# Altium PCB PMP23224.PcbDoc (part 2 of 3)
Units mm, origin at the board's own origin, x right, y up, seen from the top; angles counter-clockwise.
Board outline 180 x 75 mm, 4 copper layers (Top Layer, Signal Layer 1, Signal Layer 2, Bottom Layer), stack 1.565 mm thick; 189 components, 98 nets, 443 pads, 89 vias.
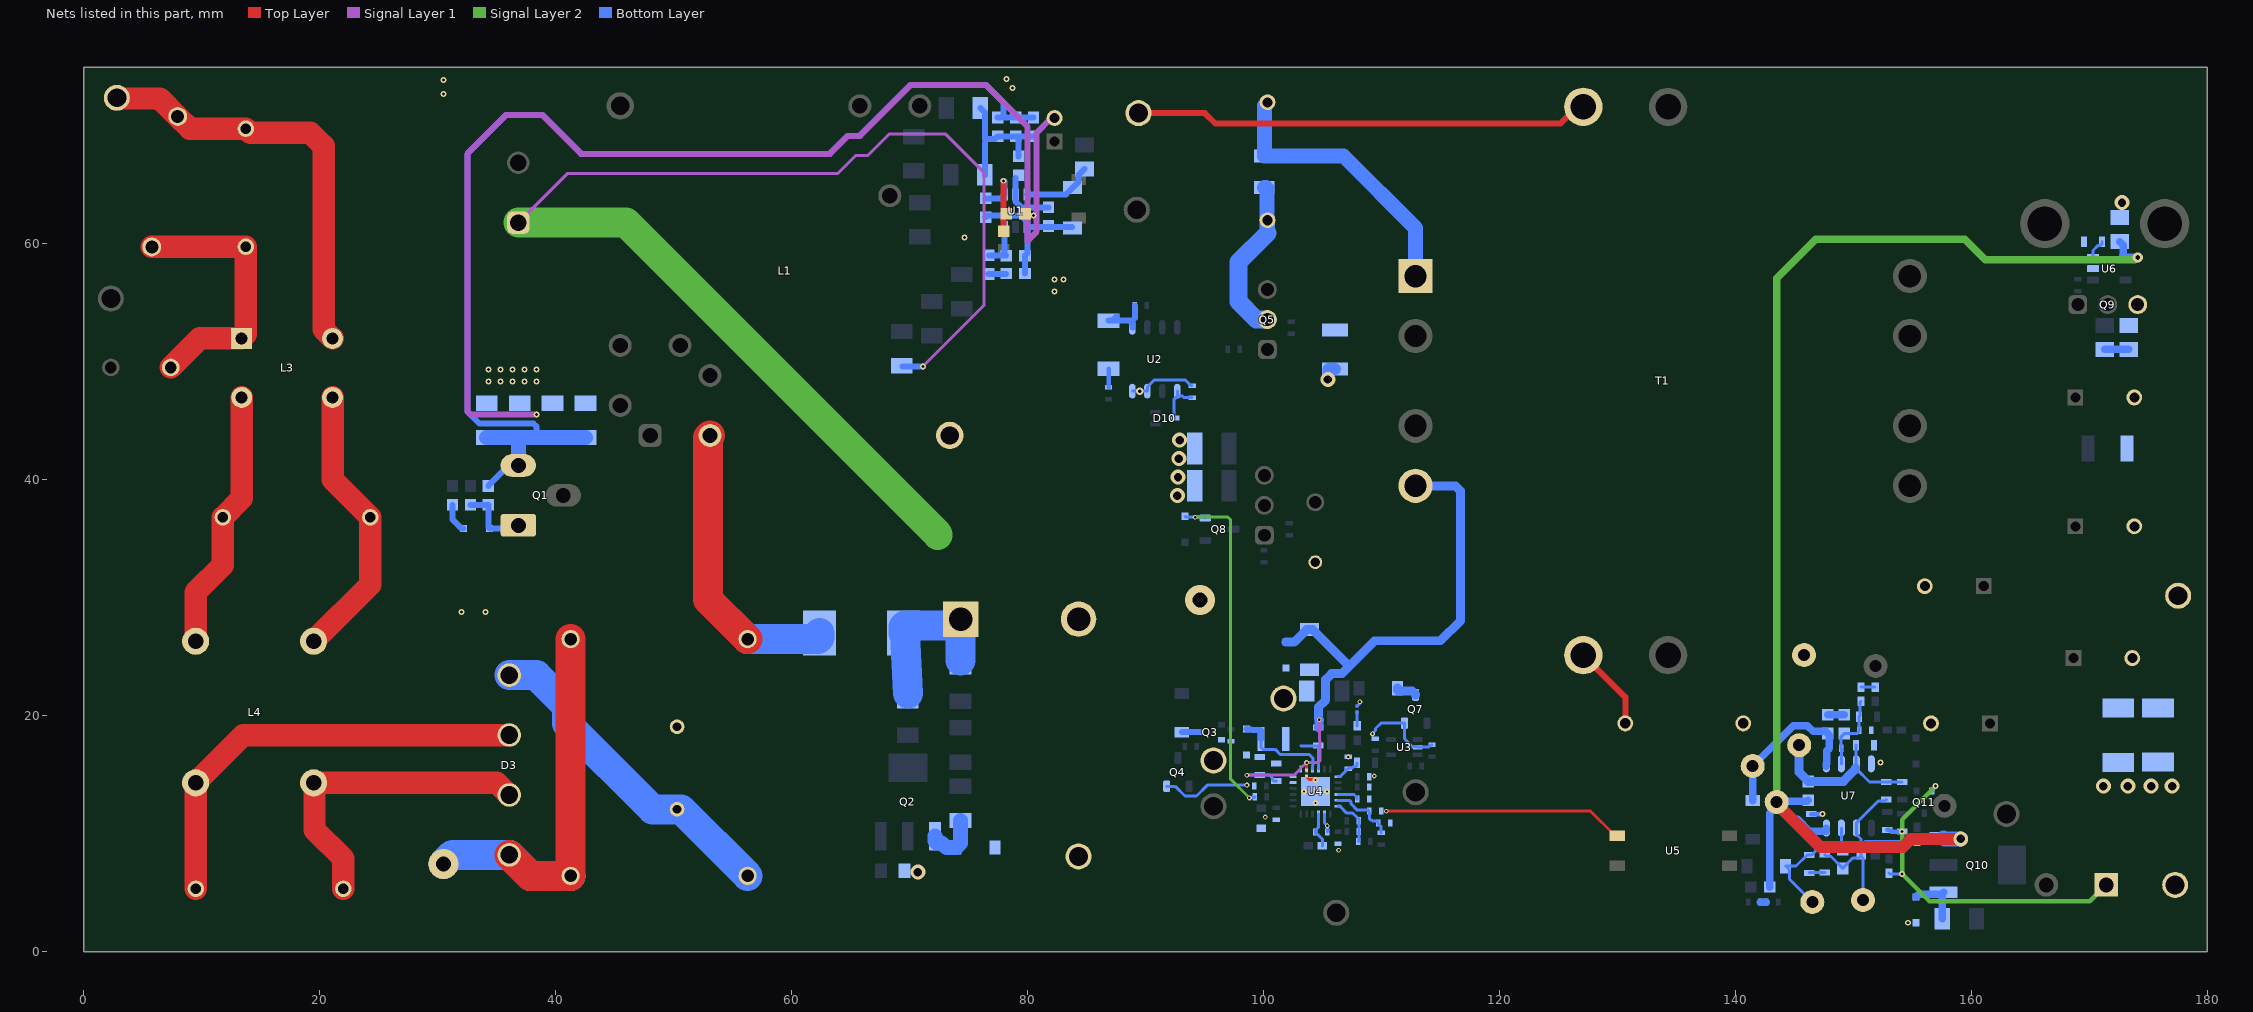
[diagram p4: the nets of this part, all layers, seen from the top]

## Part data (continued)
C2: library part 890324023025CS, "CAP, Film, 0.22 µF, X2 275 VAC, +/- 10%, TH", Cap_Case=13x7x12, Manufacturer="Wurth Elektronik", Tolerance_%=10, ValueDisplayed=0.22µF
C3 C4: "CAP, Film, 0.47 µF, X2 275 VAC, +/- 10%, TH", Cap_Case=15x10x16mm, Manufacturer="Wurth Elektronik", Supplier Part Number 1=732-5890-ND, Tolerance_%=10, ValueDisplayed=0.47µF
C5 C6: library part CMP-0012307-3, "CAP, Film, 1 uF, 450 V, +/- 5%, TH", Cap_Case=18x9.5mm, Manufacturer=Rubycon, Supplier Part Number 1=1189-1822-ND, Tolerance_%=5%, Value1=Unknown, Value2=450V, ValueDisplayed=1uF
C7: "CAP, CERM, 10 pF, 1000 V,+/- 5%, C0G/NP0, 1206", Cap_Case=1206, Manufacturer=Vishay-Vitramon, Supplier Part Number 1=720-1010-1-ND, TempCo=C0G/NP0, Tolerance_%=5, Value2=1000V, ValueDisplayed=10pF
C8: "CAP, CERM, 3900 pF, 25 V,+/- 10%, X7R, 0603", Cap_Case=0603, Manufacturer=MuRata, Supplier Part Number 1=GRM188R71E392KA01D-ND, TempCo=X7R, Tolerance_%=10, Value2=25V, ValueDisplayed=3900pF
C9: "CAP, CERM, 560 pF, 50 V,+/- 5%, C0G/NP0, 0603", Cap_Case=0603, Manufacturer=AVX, Supplier Part Number 1=478-1184-1-ND, TempCo=C0G/NP0, Tolerance_%=5, Value1="0.059 ohm", Value2=50V, ValueDisplayed=560pF
C10: "CAP, CERM, 0.22 µF, 16 V,+/- 10%, X7R, 0603", Cap_Case=0603, Manufacturer="Wurth Elektronik", Supplier Part Number 1=710-885012206048, TempCo=X7R, Tolerance_%=10, Value2=16V, ValueDisplayed=0.22µF
C11: "CAP, AL, 10 µF, 50 V, +/- 20%, TH", Cap_Case=5x11mm, Manufacturer=Panasonic, Supplier Part Number 1=P5567-ND, Tolerance_%=20, Value2=50V, ValueDisplayed=10µF
C12: "CAP, CERM, 0.068 µF, 50 V,+/- 10%, X5R, 0603", Cap_Case=0603, Manufacturer=TDK, Supplier Part Number 1=445-14157-1-ND, TempCo=X5R, Tolerance_%=10, Value1="0.035979 ohm", Value2=50V, ValueDisplayed=0.068µF
C13: "CAP, CERM, 0.47 µF, 50 V,+/- 10%, X7R, AEC-Q200 Grade 1, 1206", Cap_Case=1206, Manufacturer=TDK, Supplier Part Number 1=445-5700-1-ND, TempCo=X7R, Tolerance_%=10, Value1="0.009426 ohm", Value2=50V, ValueDisplayed=0.47µF
C14: "CAP, CERM, 10 pF, 10 V,+/- 10%, X7R, 0603", Cap_Case=0603, Manufacturer=AVX, Supplier Part Number 1=0603ZC100KAT2A-ND, TempCo=X7R, Tolerance_%=10, Value1=Unknown, Value2=10V, ValueDisplayed=10pF
C15: "CAP, CERM, 1000 pF, 100 V,+/- 10%, X7R, 0603", Cap_Case=0603, Manufacturer=AVX, Supplier Part Number 1=478-1199-1-ND, TempCo=X7R, Tolerance_%=10, Value1="0.276 ohm", Value2=100V, ValueDisplayed=1000pF
C16: library part CMP-0007728-2, "CAP, CERM, 1 uF, 25 V, +/- 10%, X7R, 0805", Cap_Case=0805, Manufacturer=Kemet, Supplier Part Number 1=399-8004-1-ND, TempCo=X7R, Tolerance_%=10%, Value1=Unknown, Value2=25V, ValueDisplayed=1uF
C17: library part CMP-0009076-1, "CAP, CERM, 0.1 uF, 630 V, +/- 10%, X7R, 1210", Cap_Case=1210, Manufacturer=Kemet, Supplier Part Number 1=399-13490-1-ND, TempCo=X7R, Tolerance_%=10%, Value1=Unknown, Value2=630V, ValueDisplayed=0.1uF
C18: library part CMP-0012326-3, "CAP, Film, 0.47 uF, 250 V, +/- 10%, TH", Cap_Case="Radial 13x6x12mm", Manufacturer=TDK, Supplier Part Number 1=495-2440-ND, Tolerance_%=10%, Value1=Unknown, Value2=250V, ValueDisplayed=0.47uF
C19: library part CMP-0006669-2, "CAP, CERM, 0.047 uF, 25 V, +/- 10%, X7R, 0402", Cap_Case=0402, Manufacturer=MuRata, Supplier Part Number 1=490-3254-1-ND, TempCo=X7R, Tolerance_%=10%, Value1=Unknown, Value2=25V, ValueDisplayed=0.047uF
C20: library part CMP-0006658-2, "CAP, CERM, 0.01 uF, 25 V, +/- 10%, X7R, 0402", Cap_Case=0402, Manufacturer=MuRata, Supplier Part Number 1=490-1312-1-ND, TempCo=X7R, Tolerance_%=10%, Value1=Unknown, Value2=25V, ValueDisplayed=0.01uF
C21: library part CMP-0086279-1, "CAP, CERM, 2200 pF, 250 V,+/- 20%, E, Dia 9mm", Cap_Case=9x4mm, Manufacturer=MuRata, TempCo=E, Tolerance_%=20%, Value2=250V, ValueDisplayed=2200pF
C22: library part CMP-0008655-2, "CAP, CERM, 33 µF, 25 V, +/- 20%, X5R, 1206", Cap_Case=1206_180, Manufacturer=TDK, Supplier Part Number 1=445-8046-1-ND, TempCo=X5R, Tolerance_%=20%, Value1="0.002648 ohm", Value2=25V, ValueDisplayed=33uF
C23 C25: library part CMP-0007355-3, "CAP, CERM, 10 uF, 35 V, +/- 20%, X5R, 0603", Cap_Case=0603, Manufacturer=Nichicon, TempCo=X5R, Tolerance_%=20%, Value1=Unknown, Value2=35V, ValueDisplayed=10uF
C24: library part CMP-0007009-5, "CAP, CERM, 6.8 µF, 25 V, +/- 10%, X5R, 0603", Cap_Case=0603, Manufacturer=TDK, Supplier Part Number 1=445-14145-6-ND, TempCo=X5R, Tolerance_%=10%, Value1="0.004211 ohm", Value2=25V, ValueDisplayed=6.8uF
C26: library part CMP-0006441-2, "CAP, CERM, 24 pF, 50 V, +/- 5%, C0G/NP0, 0402", Cap_Case=0402, Manufacturer=MuRata, Supplier Part Number 1=81-GRM1555C1H240JA1D, TempCo=C0G/NP0, Tolerance_%=5%, Value1=Unknown, Value2=50V, ValueDisplayed=24pF
C27: library part CMP-0006687-2, "CAP, CERM, 330 pF, 50 V, +/- 10%, X7R, 0402", Cap_Case=0402, Manufacturer=MuRata, Supplier Part Number 1=490-3247-1-ND, TempCo=X7R, Tolerance_%=10%, Value1=Unknown, Value2=50V, ValueDisplayed=330pF
C28: library part CMP-0006608-2, "CAP, CERM, 1 µF, 25 V, +/- 10%, X5R, 0402", Cap_Case=0402, Manufacturer=MuRata, Supplier Part Number 1=490-10017-1-ND, TempCo=X5R, Tolerance_%=10%, Value1=Unknown, Value2=25V, ValueDisplayed=1uF
C29 C30 C31: library part CMP-0006410-2, "CAP, CERM, 100 pF, 50 V, +/- 5%, C0G/NP0, 0402", Cap_Case=0402, Manufacturer=MuRata, Supplier Part Number 1=81-GRM1555C1H101JA1D, TempCo=C0G/NP0, Tolerance_%=5%, Value1=Unknown, Value2=50V, ValueDisplayed=100pF
C32: library part CMP-0006648-2, "CAP, CERM, 0.22 µF, 16 V, +/- 10%, X7R, 0402", Cap_Case=0402, Manufacturer=MuRata, Supplier Part Number 1=490-5418-1-ND, TempCo=X7R, Tolerance_%=10%, Value1=Unknown, Value2=16V, ValueDisplayed=0.22uF
C33: library part CMP-0009103-1, "CAP, CERM, 10 uF, 50 V, +/- 10%, X5R, 1210", Cap_Case=1210, Manufacturer=TDK, Supplier Part Number 1=445-9074-6-ND, TempCo=X5R, Tolerance_%=10%, Value1=Unknown, Value2=50V, ValueDisplayed=10uF
C34 C35 C36 C37 C38: library part CMP-0010480-1, "CAP, AL, 470 uF, 25 V, +/- 20%, AEC-Q200 Grade 2, TH", Cap_Case=10x16mm, Manufacturer=Chemi-Con, Supplier Part Number 1=565-1958-ND, Tolerance_%=20%, Value1=Unknown, Value2=25V, ValueDisplayed=470uF
C39: library part CMP-0081666-1, "CAP, CERM, 330 pF, 250 V,+/- 5%, C0G/NP0, 0805", Cap_Case=0805, Manufacturer=MuRata, Supplier Part Number 1=490-14654-1-ND, TempCo=C0G/NP0, Tolerance_%=5%, Value2=250V, ValueDisplayed=330pF
C40: library part CMP-0075366-1, "CAP, CERM, 2.2 µF, 25 V,+/- 10%, X7S, 0603", Cap_Case=0603, Manufacturer=MuRata, Supplier Part Number 1=490-12732-1-ND, TempCo=X7S, Tolerance_%=10%, Value2=25V, ValueDisplayed=2.2µF
C41 C47 C48: library part CMP-0007405-4, "CAP, CERM, 1 uF, 25 V, +/- 10%, X7R, 0603", Cap_Case=0603, Manufacturer=MuRata, PartNumber=GRM188R71E105KA12D, Supplier Part Number 1=490-5307-1-ND, TempCo=X7R, Tolerance_%=10%, Value1=Unknown, Value2=25V, ValueDisplayed=1uF
C42: library part CMP-0007832-2, "CAP, CERM, 1 uF, 50 V, +/- 10%, X5R, 0805", Cap_Case=0805, Manufacturer=TDK, Supplier Part Number 1=445-7622-1-ND, TempCo=X5R, Tolerance_%=10%, Value1="0.008782 ohm", Value2=50V, ValueDisplayed=1uF
C43: library part CMP-0006377-1, "CAP, CERM, 33 pF, 25 V, +/- 5%, C0G/NP0, 0402", Cap_Case=0402, Manufacturer=MuRata, Supplier Part Number 1=81-GRM1555C1E330JA1D, TempCo=C0G/NP0, Tolerance_%=5%, Value1=Unknown, Value2=25V, ValueDisplayed=33pF
C44: library part CMP-0006686-1, "CAP, CERM, 2700 pF, 50 V, +/- 10%, X7R, 0402", Cap_Case=0402, Manufacturer=MuRata, Supplier Part Number 1=490-1306-1-ND, TempCo=X7R, Tolerance_%=10%, Value1=Unknown, Value2=50V, ValueDisplayed=2700pF
C45: library part CMP-0006681-2, "CAP, CERM, 0.018 uF, 50 V, +/- 10%, X7R, 0402", Cap_Case=0402, Manufacturer=MuRata, Supplier Part Number 1=GRM155R71H183KA12D-ND, TempCo=X7R, Tolerance_%=10%, Value1=Unknown, Value2=50V, ValueDisplayed=0.018uF
C46: library part CMP-0007377-1, "CAP, CERM, 0.01 uF, 16 V, +/- 10%, X7R, 0603", Cap_Case=0603, Manufacturer=MuRata, Supplier Part Number 1=490-1525-1-ND, TempCo=X7R, Tolerance_%=10%, Value1=Unknown, Value2=16V, ValueDisplayed=0.01uF
C49: library part CMP-0007403-2, "CAP, CERM, 0.01 uF, 25 V, +/- 10%, X7R, 0603", Cap_Case=0603, Manufacturer=MuRata, Supplier Part Number 1=490-1520-1-ND, TempCo=X7R, Tolerance_%=10%, Value1=Unknown, Value2=25V, ValueDisplayed=0.01uF
D1: library part CMP-0076883-2, "Diode, Switching, 800 V, 3 A, SMC", Manufacturer=Vishay-Semiconductor, Value1=3A, Value2=1.3V
D2: library part STTH506DTI, "DIODE GEN PURP 600V 8A TO220FP", Manufacturer=STMicroelectronics
D3: library part CMP-0029222-2, "Diode, Switching-Bridge, 420 V, 8 A, TH", Manufacturer="Micro Commercial Components", Supplier Part Number 1=GBU8J-BPMS-ND, Value1=8A, Value2=1V
D4: "Diode, Switching, 100 V, 0.2 A, SOD-323", Manufacturer="Micro Commercial Components", Supplier Part Number 1=MMDL914-TPMSCT-ND, Value1=0.2A, Value2=1V
D5: "Diode, Switching, 100 V, 0.15 A, SOD-123FL", Manufacturer=Vishay-Semiconductor, Supplier Part Number 1=1N4148WFL-G3-08GICT-ND, Value1=0.15A, Value2=1.2V
D6: library part CMP-0085137-1, "Diode, Zener, 16 V, 500 mW, SOD-123", Manufacturer="Diodes Inc.", Power_W=500mW, Value1=0.5W
D7: library part CMP-0076920-2, "Diode, Switching, 100 V, 0.15 A, SOD-123FL", Manufacturer=Vishay-Semiconductor, Value1=0.15A, Value2=1.2V
D8: library part CMP-0029162-1, "Diode, Ultrafast, 600 V, 1 A, AEC-Q101, SMAF", Manufacturer="Fairchild Semiconductor", Supplier Part Number 1=ES1JAFCT-ND, Value1=1A, Value2=1.7V
D9: library part CMP-0077074-2, "Diode, Superfast Rectifier, 600 V, 1 A, 3.5x1.6mm", Manufacturer="Comchip Technology", Value1=1A, Value2=1.7V
D10: library part CMP-0028454-2, "Diode, Schottky, 30 V, 0.2 A, SOT-523", Manufacturer="Diodes Inc.", Value1=0.2A, Value2=0.7V
D11: library part CMP-0029031-1, "Diode, Switching, 200 V, 0.2 A, SOD-123", Manufacturer="Diodes Inc.", Supplier Part Number 1=BAV21W-FDICT-ND, Value1=0.2A, Value2=1.25V
D12: library part CMP-0028882-2, "Diode, Schottky, 30 V, 0.8 A, SOD-323", Manufacturer=Toshiba, Supplier Part Number 1=CUS08F30H3FDKR-ND, Value1=0.8A
D13: library part CMP-0005823-4, "Diode, TVS, Uni, 24 V, 49 Vc, SOD-323", Manufacturer=Bourns, Value1=500W
D14: library part CMP-0005822-3, "Diode, TVS, Bi, 18 V, SOD-323", Manufacturer=Bourns, Value1=350W
D15: library part CMP-0005911-2, "Diode, Zener, 20 V, 150 mW, SOD-523F", Manufacturer="Comchip Technology", Power_W=150mW, Supplier Part Number 1=641-1043-1-ND, Value1=0.15W
D16: library part CMP-0005855-3, "Diode, Zener, 5.6 V, 200 mW, SOD-323", Manufacturer="Diodes Inc.", Power_W=200mW, Value1=0.2W
D17 D18: library part CMP-0076981-2, "Diode, Switching, 100 V, 0.2 A, SOD-123", Manufacturer="ON Semiconductor", Value1=0.2A, Value2=V
D19: library part CMP-0005829-1, "Diode, Zener, 10 V, 200 mW, SOD-323", Manufacturer="Diodes Inc.", Power_W=200mW, Supplier Part Number 1=MMSZ5240BS-FDICT-ND, Value1=0.2W
F1: "Fuse, 5 A, 250VAC/VDC, TH", Irating_A=5A, Manufacturer=Littelfuse, Supplier Part Number 1=WK4263CT-ND
H1: library part CMP-0004015-1, "Heat Sink, TO-220, TH", Manufacturer="Wakefield Solutions", PartNumber=634-10ABP, Supplier Part Number 1=345-1026-ND
J1: library part CMP-0074910-1, "Terminal Block, 5.08 mm, 2x1, Brass, TH", Color=Blue, Current_A=15A, Manufacturer="On-Shore Technology", Supplier Part Number 1=ED1609-ND, Voltage_V=300V
L1: library part CMP-0078769-1, "Inductor, 120 µH, 4 A, 0.055 ohm, TH", Manufacturer="Wurth Elektronik", Value1="0.055 ohm", Value2=4A, ValueDisplayed=120µH
L2: library part 7447020, "100µH Unshielded Toroidal Inductor 2A 80 mOhm Max Radial", Manufacturer="Wurth Elektronik", Supplier Part Number 1=732-1424-ND, Value1="0.16 ohm", Value2=2A, ValueDisplayed=100µH
L3: "Coupled inductor, 1 mH, 3 A, 0.035 ohm, TH", Manufacturer="Wurth Elektronik", Supplier Part Number 1=732-1439-ND, ValueDisplayed=1mH
L4: "Coupled inductor, 10 mH, 3 A, 0.105 ohm, TH", Manufacturer="Wurth Elektronik", Supplier Part Number 1=732-1452-ND, ValueDisplayed=10mH
L5: library part CMP-0060002-1, "Inductor, Wirewound, 22 uH, 0.49 A, 0.56 ohm, SMD", Manufacturer="Taiyo Yuden", Supplier Part Number 1=587-2439-1-ND, Value1="0.56 ohm", Value2=0.49A, ValueDisplayed=22uH
NT1 NT2: library part CMP-0078142-1, "Single point connection between nets.", Manufacturer=N/A
Q1: library part IPP60R099C7XKSA1, "MOSFET, N-CH, 600 V, 22 A, TO-220AB", Alternate Manufacturer=None, Manufacturer="Infineon Technologies", Supplier Part Number 1=IPP60R099C7XKSA1-ND, Value1="? ohm", Value2="42 nC"
Q2: library part CMP-0001204-2, "MOSFET, N-CH, 600 V, 0.3 A, SOT-223", Alternate Manufacturer=None, Manufacturer=STMicroelectronics, Supplier Part Number 1=497-3523-1-ND, Value2="4.9 nC"
Q3: library part CMP-0000015-1, "MOSFET, P-CH, -50 V, -0.13 A, SOT-323", Alternate Manufacturer=None, Manufacturer="Diodes Inc.", Supplier Part Number 1=BSS84W-FDICT-ND, Value1=1
Q4: library part CMP-0085603-1, "MOSFET, N-CH, 60 V, 0.115 A, AEC-Q101, SOT-23", Alternate Manufacturer=None, Manufacturer="Diodes Inc.", Value1="? ohm", Value2="0.223 nC"
Q5 Q6: library part CMP-0084435-1, "MOSFET, N-CH, 650 V, 9 A", Alternate Manufacturer=None, Manufacturer="Infineon Technologies", Value1="? ohm", Value2="18 nC"
Q7: library part CMP-0000947-1, "MOSFET, N-CH, 100 V, 0.17 A, SOT-23", Alternate Manufacturer=None, Manufacturer="Fairchild Semiconductor", Supplier Part Number 1=BSS123NCT-ND, Value1=1, Value2="1.8 nC"
Q8: library part CMP-0067574-2, "MOSFET, N-CH, Depletion Mode, 100 V, 0.17 A, AEC-Q101, SOT-23", Alternate Manufacturer=None, Manufacturer="Infineon Technologies", Supplier Part Number 1=BSS126H6327XTSA2CT-ND, Value1="? ohm", Value2="1.4 nC"
Q9: library part CMP-0860023-1, "MOSFET, N-CH, 200 V, 100 A,", Alternate Manufacturer=None, Manufacturer="Infineon Technologies", Value1="? ohm", Value2="70 nC"
Q10: library part CMP-0000473-1, "Transistor, NPN, 100 V, 1 A, AEC-Q101, SOT-223", Manufacturer="Diodes Inc.", Supplier Part Number 1=FZT493CT-ND, Value1="1 A", Value2=300
Q11: library part CMP-0000774-1, "MOSFET, N-CH, 60 V, 0.31 A, SOT-323", Alternate Manufacturer=None, Manufacturer="Fairchild Semiconductor", Supplier Part Number 1=2N7002KWCT-ND, Value1=1
R1 R6: "RES, 3.09 M, 1%, 0.25 W, 1206", Manufacturer=Vishay-Dale, Power_W=0.25, Supplier Part Number 1=541-3.09MFCT-ND, TempCo="100 ppm/C", Tolerance_%=1, Value1=1%, Value2=0.25W, Value_Code=3M09, ValueDisplayed=3.09M
R2 R5 R9 R15: "RES, 3.3 M, 5%, 0.25 W, 1206", Manufacturer=Vishay-Dale, Power_W=0.25, Supplier Part Number 1=541-3.3MECT-ND, TempCo="200 ppm/C", Tolerance_%=5, Value1=5%, Value2=0.25W, Value_Code=3M30, ValueDisplayed=3.3M
R3: "RES, 10.0, 1%, 0.1 W, 0603", Manufacturer=Vishay-Dale, Power_W=0.1, Supplier Part Number 1=541-10.0HCT-ND, TempCo="100 ppm/C", Tolerance_%=1, Value1=1%, Value2=0.1W, Value_Code=10R0, ValueDisplayed=10.0
R4: "RES, 82.5 k, 1%, 0.1 W, 0603", Manufacturer=Vishay-Dale, Power_W=0.1, Supplier Part Number 1=541-82.5KHCT-ND, TempCo="100 ppm/C", Tolerance_%=1, Value1=1%, Value2=0.1W, Value_Code=82k5, ValueDisplayed=82.5k
R7: "RES, 1.00, 1%, 0.1 W, 0603", Manufacturer=Vishay-Dale, Power_W=0.1, Supplier Part Number 1=52K8059, TempCo="100 ppm/C", Tolerance_%=1, Value1=1%, Value2=0.1W, Value_Code=1R00, ValueDisplayed=1.00
R8: "RES, 24.3 k, 1%, 0.1 W, 0603", Manufacturer=Vishay-Dale, Power_W=0.1, Supplier Part Number 1=541-24.3KHCT-ND, TempCo="100 ppm/C", Tolerance_%=1, Value1=1%, Value2=0.1W, Value_Code=24k3, ValueDisplayed=24.3k
R10: "RES, 3.0 k, 5%, 0.1 W, 0603", Manufacturer=Vishay-Dale, Power_W=0.1, Supplier Part Number 1=541-3.0KGCT-ND, TempCo="200 ppm/C", Tolerance_%=5, Value1=5%, Value2=0.1W, Value_Code=3k00, ValueDisplayed=3.0k
R11 R12: "RES, 0.13, 1%, 0.5 W, 1206", Manufacturer="Stackpole Electronics Inc", Power_W=0.5, Supplier Part Number 1=CSR1206FTR130CT-ND, TempCo="100 ppm/C", Tolerance_%=1, Value1=1%, Value2=0.5W, Value_Code=R130, ValueDisplayed=0.13
R13 R14: "RES, 0.15, 1%, 0.5 W, 1206", Manufacturer=Panasonic, Power_W=0.5, Supplier Part Number 1=P16006CT-ND, TempCo="250 ppm/C", Tolerance_%=1, Value1=1%, Value2=0.5W, Value_Code=R150, ValueDisplayed=0.15
R16: library part CMP-0022260-1, "RES, 28.0 k, 1%, 0.1 W, 0603", Manufacturer=Vishay-Dale, Power_W=100mW, Supplier Part Number 1=541-28.0KHCT-ND, TempCo="100 ppm/C", Tolerance_%=1%, Value2=0.1W, Value_Code=28k0, ValueDisplayed=28.0k
R17: "RES, 10.0, 1%, 0.125 W, 0805", Manufacturer=Vishay-Dale, Power_W=0.125, Supplier Part Number 1=541-10.0CCT-ND, TempCo="100 ppm/C", Tolerance_%=1, Value1=1%, Value2=0.125W, Value_Code=10R0, ValueDisplayed=10.0
R18: "RES, 140 k, 1%, 0.1 W, 0603", Manufacturer=Vishay-Dale, Power_W=0.1, Supplier Part Number 1=541-140KHCT-ND, TempCo="100 ppm/C", Tolerance_%=1, Value1=1%, Value2=0.1W, Value_Code=140k
R19 R22 R23: library part CMP-0016959-3, "RES, 3.24 M, 1%, 0.25 W, AEC-Q200 Grade 0, 1206", Manufacturer=Vishay-Dale, Power_W=250mW, Supplier Part Number 1=541-3.24MFCT-ND, TempCo="100 ppm/C", Tolerance_%=1%, Value2=0.25W, Value_Code=3M24, ValueDisplayed=3.24M
R20: library part CMP-0017052-1, "RES, 51.1 k, 1%, 0.25 W, 1206", Manufacturer=Vishay-Dale, Power_W=250mW, Supplier Part Number 1=541-51.1KFCT-ND, TempCo="100 ppm/C", Tolerance_%=1%, Value2=0.25W, Value_Code=51k1, ValueDisplayed=51.1k
R21 R57: library part CMP-0022532-2, "RES, 60.4 k, 1%, 0.1 W, 0603", Manufacturer=Vishay-Dale, Power_W=100mW, Supplier Part Number 1=541-60.4KHCT-ND, TempCo="100 ppm/C", Tolerance_%=1%, Value2=0.1W, Value_Code=60k4, ValueDisplayed=60.4k
R24: library part CMP-0018673-3, "RES, 3.3 M, 5%, 0.25 W, AEC-Q200 Grade 0, 1206", Manufacturer=Vishay-Dale, Power_W=250mW, Supplier Part Number 1=541-3.3MECT-ND, TempCo="200 ppm/C", Tolerance_%=5%, Value2=0.25W, Value_Code=3M30, ValueDisplayed=3.3M
R25 R26: library part CMP-0025950-1, "RES, 100 k, 1%, 0.063 W, 0402", Manufacturer=Vishay-Dale, Power_W=63mW, Supplier Part Number 1=541-100KLCT-ND, TempCo="100 ppm/C", Tolerance_%=1%, Value2=0.063W, Value_Code=100k
R27: library part CMP-0026942-3, "RES, 4.7, 5%, 0.063 W, AEC-Q200 Grade 0, 0402", Manufacturer=Vishay-Dale, Power_W=63mW, Supplier Part Number 1=541-4.7JCT-ND, TempCo="200 ppm/C", Tolerance_%=5%, Value2=0.063W, Value_Code=4R70, ValueDisplayed=4.7
R28 R30: library part CMP-0026843-3, "RES, 15, 5%, 0.063 W, AEC-Q200 Grade 0, 0402", Manufacturer=Vishay-Dale, Power_W=63mW, Supplier Part Number 1=541-15JCT-ND, TempCo="200 ppm/C", Tolerance_%=5%, Value2=0.063W, Value_Code=15R0, ValueDisplayed=15
R29 R31: library part CMP-0026825-5, "RES, 10 k, 5%, 0.063 W, AEC-Q200 Grade 0, 0402", Manufacturer=Vishay-Dale, Power_W=63mW, Supplier Part Number 1=541-10KJCT-ND, TempCo="200 ppm/C", Tolerance_%=5%, Value2=0.063W, Value_Code=10k0, ValueDisplayed=10k
R32 R34: library part CMP-0026302-1, "RES, 348 k, 1%, 0.063 W, 0402", Manufacturer=Vishay-Dale, Power_W=63mW, Supplier Part Number 1=541-348KLCT-ND, TempCo="100 ppm/C", Tolerance_%=1%, Value2=0.063W, Value_Code=348k
R33: library part CMP-0026071-1, "RES, 1.00 k, 1%, 0.063 W, 0402", Manufacturer=Vishay-Dale, Power_W=63mW, Supplier Part Number 1=541-1.00KLCT-ND, TempCo="100 ppm/C", Tolerance_%=1%, Value2=0.063W, Value_Code=1k00, ValueDisplayed=1.00k
R35 R36: library part CMP-0015329-1, "RES, 0.18, 5%, 0.25 W, 1210", Manufacturer=Panasonic, Power_W=250mW, Supplier Part Number 1=P.18SCT-ND, TempCo="200 ppm/C", Tolerance_%=5%, Value2=0.25W, Value_Code=R180, ValueDisplayed=0.18
R37: library part CMP-0026402-2, "RES, 499, 1%, 0.063 W, AEC-Q200 Grade 0, 0402", Manufacturer=Vishay-Dale, Power_W=63mW, Supplier Part Number 1=541-499LCT-ND, TempCo="100 ppm/C", Tolerance_%=1%, Value2=0.063W, Value_Code=499R, ValueDisplayed=499
R38: library part CMP-0021459-2, "RES, 84.5 k, 1%, 0.125 W, 0805", Manufacturer=Vishay-Dale, Power_W=125mW, Supplier Part Number 1=541-84.5KCCT-ND, TempCo="100 ppm/C", Tolerance_%=1%, Value2=0.125W, Value_Code=84k5, ValueDisplayed=84.5k
R39: library part CMP-0026395-1, "RES, 47.5 k, 1%, 0.063 W, 0402", Manufacturer=Vishay-Dale, Power_W=63mW, Supplier Part Number 1=541-47.5KLCT-ND, TempCo="100 ppm/C", Tolerance_%=1%, Value2=0.063W, Value_Code=47k5, ValueDisplayed=47.5k
R40: library part CMP-0026859-2, "RES, 1.0 M, 5%, 0.063 W, AEC-Q200 Grade 0, 0402", Manufacturer=Vishay-Dale, Power_W=63mW, Supplier Part Number 1=541-1.0MJCT-ND, TempCo="200 ppm/C", Tolerance_%=5%, Value2=0.063W, Value_Code=1M00, ValueDisplayed=1.0M
R41: library part CMP-0026875-1, "RES, 20 k, 5%, 0.063 W, 0402", Manufacturer=Vishay-Dale, Power_W=63mW, Supplier Part Number 1=541-20KJCT-ND, TempCo="200 ppm/C", Tolerance_%=5%, Value2=0.063W, Value_Code=20k0, ValueDisplayed=20k
R42 R44: library part CMP-0026065-1, "RES, 196 k, 1%, 0.063 W, 0402", Manufacturer=Vishay-Dale, Power_W=63mW, Supplier Part Number 1=541-196KLCT-ND, TempCo="100 ppm/C", Tolerance_%=1%, Value2=0.063W, Value_Code=196k
R43 R45 R51: library part CMP-0026822-3, "RES, 0, 5%, 0.063 W, AEC-Q200 Grade 0, 0402", Manufacturer=Vishay-Dale, Power_W=63mW, Supplier Part Number 1=541-0.0JCT-ND, TempCo="200 ppm/C", Tolerance_%=5%, Value2=0.063W, Value_Code=0000, ValueDisplayed=0
R46: library part CMP-0026021-1, "RES, 150 k, 1%, 0.063 W, 0402", Manufacturer=Vishay-Dale, Power_W=63mW, Supplier Part Number 1=541-150KLCT-ND, TempCo="100 ppm/C", Tolerance_%=1%, Value2=0.063W, Value_Code=150k
R47: library part CMP-0026445-1, "RES, 53.6 k, 1%, 0.063 W, 0402", Manufacturer=Vishay-Dale, Power_W=63mW, Supplier Part Number 1=541-53.6KLCT-ND, TempCo="100 ppm/C", Tolerance_%=1%, Value2=0.063W, Value_Code=53k6, ValueDisplayed=53.6k
R48: library part CMP-0020168-2, "RES, 53.6, 0.1%, 0.125 W, 0805", Manufacturer="Yageo America", Power_W=125mW, TempCo="25 ppm/C", Tolerance_%=0.1%, Value2=0.125W, Value_Code=53R6, ValueDisplayed=53.6
R49 R50: library part CMP-0016532-1, "RES, 0.01, 1%, 1 W, 2010", Manufacturer="Stackpole Electronics Inc", Power_W=1W, Supplier Part Number 1=CSRN2010FT10L0CT-ND, TempCo="250 ppm/C", Tolerance_%=1%, Value_Code=R010, ValueDisplayed=0.01
R52: library part CMP-0025963-1, "RES, 10.0, 1%, 0.063 W, 0402", Manufacturer=Vishay-Dale, Power_W=63mW, Supplier Part Number 1=541-10.0LCT-ND, TempCo="100 ppm/C", Tolerance_%=1%, Value2=0.063W, Value_Code=10R0, ValueDisplayed=10.0
R53: library part CMP-0026329-1, "RES, 3.01 k, 1%, 0.063 W, 0402", Manufacturer=Vishay-Dale, Power_W=63mW, Supplier Part Number 1=541-3.01KLCT-ND, TempCo="100 ppm/C", Tolerance_%=1%, Value2=0.063W, Value_Code=3k01, ValueDisplayed=3.01k
R54: library part CMP-0016577-2, "RES, 10.0 k, 1%, 0.25 W, 1206", Manufacturer=Vishay-Dale, Power_W=250mW, Supplier Part Number 1=541-10.0KFCT-ND, TempCo="100 ppm/C", Tolerance_%=1%, Value2=0.25W, Value_Code=10k0, ValueDisplayed=10.0k
R55 R67: library part CMP-0021990-4, "RES, 100 k, 1%, 0.1 W, AEC-Q200 Grade 0, 0603", Manufacturer=Vishay-Dale, PartNumber=CRCW0603100KFKEA, Power_W=100mW, Supplier Part Number 1=541-100KHCT-ND, TempCo="100 ppm/C", Tolerance_%=1%, Value2=0.1W, Value_Code=100k
R56: library part CMP-0025729-1, "RES, 1.0 k, 5%, 0.1 W, 0603", Manufacturer=Vishay-Dale, Power_W=100mW, Supplier Part Number 1=541-1.0KGCT-ND, TempCo="200 ppm/C", Tolerance_%=5%, Value2=0.1W, Value_Code=1k00, ValueDisplayed=1.0k
R58: library part CMP-0025768-2, "RES, 2.0 k, 5%, 0.1 W, 0603", Manufacturer=Vishay-Dale, Power_W=100mW, Supplier Part Number 1=541-2.0KGCT-ND, TempCo="200 ppm/C", Tolerance_%=5%, Value2=0.1W, Value_Code=2k00, ValueDisplayed=2.0k
R59: library part CMP-0026022-3, "RES, 150, 1%, 0.063 W, AEC-Q200 Grade 0, 0402", Manufacturer=Vishay-Dale, Power_W=63mW, Supplier Part Number 1=541-150LCT-ND, TempCo="100 ppm/C", Tolerance_%=1%, Value2=0.063W, Value_Code=150R, ValueDisplayed=150
R60: library part CMP-0025993-1, "RES, 12.7 k, 1%, 0.063 W, 0402", Manufacturer=Vishay-Dale, Power_W=63mW, Supplier Part Number 1=541-12.7KLCT-ND, TempCo="100 ppm/C", Tolerance_%=1%, Value2=0.063W, Value_Code=12k7, ValueDisplayed=12.7k
R61 R62: library part CMP-0025686-1, "RES, 10.0 k, 0.1%, 0.1 W, AEC-Q200 Grade 1, 0603", Manufacturer=Vishay-Dale, Power_W=100mW, Supplier Part Number 1=TNP10.0KAACT-ND, TempCo="25 ppm/C", Tolerance_%=0.1%, Value2=0.1W, Value_Code=10k0, ValueDisplayed=10.0k
R63: library part CMP-0026064-2, "RES, 191, 1%, 0.063 W, 0402", Manufacturer=Vishay-Dale, Power_W=63mW, Supplier Part Number 1=541-191LCT-ND, TempCo="100 ppm/C", Tolerance_%=1%, Value2=0.063W, Value_Code=191R, ValueDisplayed=191
R64: library part CMP-0026620-1, "RES, 9.31 k, 1%, 0.063 W, 0402", Manufacturer=Vishay-Dale, Power_W=63mW, Supplier Part Number 1=541-9.31KLCT-ND, TempCo="100 ppm/C", Tolerance_%=1%, Value2=0.063W, Value_Code=9k31, ValueDisplayed=9.31k
R65: library part CMP-0023624-3, "RES, 9.76 k, 0.1%, 0.1 W, 0603", Manufacturer="Susumu Co Ltd", Power_W=100mW, Supplier Part Number 1=RG16P9.76KBCT-ND, TempCo="25 ppm/C", Tolerance_%=0.1%, Value2=0.1W, Value_Code=9k76, ValueDisplayed=9.76k
R66: library part CMP-0026455-1, "RES, 576 k, 1%, 0.063 W, 0402", Manufacturer=Vishay-Dale, Power_W=63mW, Supplier Part Number 1=541-576KLCT-ND, TempCo="100 ppm/C", Tolerance_%=1%, Value2=0.063W, Value_Code=576k
R68: library part CMP-0021998-4, "RES, 10.0 k, 1%, 0.1 W, AEC-Q200 Grade 0, 0603", Manufacturer=Vishay-Dale, PartNumber=CRCW060310K0FKEA, Power_W=100mW, Supplier Part Number 1=541-10.0KHCT-ND, TempCo="100 ppm/C", Tolerance_%=1%, Value2=0.1W, Value_Code=10k0, ValueDisplayed=10.0k
RT1: library part CMP-0002523-3, "Thermistor NTC, 47k ohm, 5%, 0603", Manufacturer=MuRata, Power_W=100mW, Supplier Part Number 1=490-2428-1-ND, Tolerance_%=5%
RV1: "Varistor 275V RMS 10MM Radial, TH", Manufacturer="EPCOS Inc", Supplier Part Number 1=495-1433-ND
T1: library part CMP-0095835-1, "Flyback for PMP23224", Manufacturer="Renco Electronics", Operating Temperature Range=to, Voltage_Isolation_Vrms=3kV
TP1 TP4 TP5 TP6 TP8 TP9 TP10: library part CMP-0055147-1, "Test Point, Multipurpose, Red, TH", Color=Red, Manufacturer=Keystone, Supplier Part Number 1=36-5010-ND
TP2 TP7 TP11 TP12: library part CMP-0055148-1, "Test Point, Multipurpose, Black, TH", Color=Black, Manufacturer=Keystone, Supplier Part Number 1=36-5011-ND
TP3: library part CMP-0003907-1, "PIGTAIL", Manufacturer="Texas Instruments"
TP13 TP14 TP15 TP16 TP18 TP19 TP20: library part CMP-0055140-1, "Test Point, Miniature, Orange, TH", Color=Orange, Manufacturer=Keystone, Supplier Part Number 1=36-5003-ND
TP17: library part CMP-0055138-1, "Test Point, Miniature, Black, TH", Color=Black, Manufacturer=Keystone, Supplier Part Number 1=36-5001-ND
TP_L1: "Test Point, Multipurpose, Red, TH", Color=Red, Manufacturer=Keystone, Supplier Part Number 1=36-5010-ND
TP_N1: library part CMP-0055148-2, "Test Point, Multipurpose, Black, TH", Color=Black, Manufacturer="Keystone Electronics", PartNumber=5011, Supplier Part Number 1=36-5011-ND
U1: "6-Pin Single-Phase Transition-Mode PFC Controller, DBV0006A (SOT-23-6)", Alternate Manufacturer="Texas Instruments"
U2: library part CMP-0077706-1, "3-kVRMS Single-Channel Isolated Gate Drivers, D0008B (SOIC-8)", Alternate Manufacturer="Texas Instruments", Alternate PartNumber=UCC5350SBD
U3: library part CMP-0860894-1, "Low power, small size comparator with push-pull output, DCK0005A (SOT-SC70-5)", Alternate Manufacturer="Texas Instruments", Alternate PartNumber=TLV7011DCKT, Operating Temperature Range="-40 to 125 C", Rating=Catalog
U4: library part CMP-0086087-1, "UCC28782ADRTW, RTW0024B (WQFN-24)", Alternate Manufacturer="Texas Instruments"
U5: library part CMP-0006160-3, "Optocoupler, 5 kV, 63-125% CTR, SMT", Manufacturer=Vishay-Semiconductor, Supplier Part Number 1=VOL618A-2TCT-ND, Voltage_Isolation_Vrms=5kV
U6: library part CMP-0013047-3, "High-Frequency Multi-Mode Synchronous Rectifier Controller, DBV0005A (SOT-23-5)", Alternate Manufacturer="Texas Instruments", Alternate PartNumber=UCC24612-2DBVR
U7: library part CMP-0043686-1, "Dual Operational Amplifier with Internal Reference, 3 to 32 V, -40 to 105 degC, 8-pin SOIC (D8), Green (RoHS & no Sb/Br)", Manufacturer="Texas Instruments", PartNumber=TL103WAID, Rating=Catalog, Total Supply Voltage(Max)(+5V is 5, +/-5V is 10)=32, Total Supply Voltage(Min)(+5V is 5, +/-5V is 10)=3

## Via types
v1: diameter 0.508, hole 0.254, Top Layer to Bottom Layer, 41 vias
v2: diameter 0.406, hole 0.203, Top Layer to Bottom Layer, 23 vias
v3: diameter 1.27, hole 0.711, Top Layer to Bottom Layer, 12 vias
v4: diameter 0.5, hole 0.2, Top Layer to Bottom Layer, 5 vias
v5: diameter 0.864, hole 0.406, Top Layer to Bottom Layer, 4 vias
v6: diameter 2.54, hole 1.27, Top Layer to Bottom Layer, 2 vias
v7: diameter 0.635, hole 0.305, Top Layer to Bottom Layer, 2 vias

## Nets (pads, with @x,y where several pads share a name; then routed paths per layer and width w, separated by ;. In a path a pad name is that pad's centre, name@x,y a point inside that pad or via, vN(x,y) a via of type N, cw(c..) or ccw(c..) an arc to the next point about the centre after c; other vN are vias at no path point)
BAT_GND: J1.1 Q11.2 R49.2 R50.2 R63.2 R65.1 R68.1 TP12.1 | length 30.4
  Signal Layer 2 w0.381: v1(156.972,14.032) 154.145,11.205 v1(154.145,10.172) v1(154.145,6.588) 156.459,4.274 170.059,4.274 J1.1@171.45,5.665
  Bottom Layer w0.254: R63.2@153.04,6.658 153.11,6.588 v1(154.145,6.588)
  Bottom Layer w0.381: R65.1@152.878,10.326 153.068,10.326 153.223,10.172 v1(154.145,10.172) ; Q11.2@156.663,13.641 156.663,13.705 156.972,14.015 v1(156.972,14.032)
  other v3: 171.196,14.032 173.282,14.032 175.26,14.032 177.038,14.032
BGND: C22.2 C23.2 C24.2 C25.2 D13.2 NT2.2 T1.4 U4.20 | length 54.2
  Top Layer w0.254: NT2.2@103.657,15.416 v2(103.657,16.034)
  Signal Layer 1 w0.254: v2(98.593,14.963) 102.586,14.963 v2(103.657,16.034) 104.653,16.034 104.801,16.183 104.801,17.867 104.734,17.935 v2(104.734,19.661)
  Bottom Layer w0.254: v2(98.593,14.963) 99.655,14.963 C24.2@99.678,14.986 100.503,14.986 100.774,14.715 100.774,14.579 100.901,14.452 C25.2@101.092,14.452 ; v2(103.657,16.034) 103.66,16.031 103.66,15.487 U4.20@103.664,15.484
  Bottom Layer w0.762: D13.2@101.926,26.246 102.606,26.246 103.664,27.304 C22.2@103.914,27.304 104.164,27.304 107.152,24.316 107.385,24.316 ; C23.2@104.664,19.004 104.727,19.067 104.727,19.655 v2(104.734,19.661) 104.664,19.73 104.664,20.726 105.266,21.329 105.266,23.072 105.773,23.579 106.648,23.579 107.385,24.316 ; T1.4@112.89,39.497 116.276,39.497 116.723,39.051 116.723,28.077 115.008,26.362 109.431,26.362 107.385,24.316
"bias 5V": C41.2 C42.1 Q10.3 R56.2 R58.2 TP14.1 U6.4 U7.8 | length 114.6
  Top Layer w1.016: TP14.1@143.51,12.701 143.51,12.56 147.18,8.89 154.223,8.89 154.896,9.562 v3(159.114,9.562)
  Signal Layer 2 w0.635: TP14.1@143.51,12.701 143.51,57.108 146.812,60.41 159.449,60.41 161.186,58.674 173.876,58.674 174.055,58.853 v5(174.117,58.853)
  Bottom Layer w0.635: R58.2@142.918,5.48 142.918,11.731 143.51,12.323 TP14.1@143.51,12.701 ; R56.2@146.182,12.834 146.116,12.767 143.577,12.767 TP14.1@143.51,12.701 ; U7.8@147.72,10.483 147.72,10.225 147.703,10.207 146.5,10.207 C41.2@146.436,10.144 146.373,10.144 145.291,11.226 144.985,11.226 TP14.1@143.51,12.701 ; C42.1@172.593,60.198 172.896,59.895 172.896,58.879 172.918,58.858 174.113,58.858 v5(174.117,58.853)
  Bottom Layer w1.27: Q10.3@157.654,9.65 157.741,9.562 v3(159.114,9.562)
BIN: C22.1 C23.1 D9.1 D13.1 L5.2 TP5.1 U4.22 | length 3.5
  Bottom Layer w0.254: 103.164,17.442 103.183,17.461 104.645,17.461 C23.1@104.664,17.48 U4.22@104.664,15.484
BSW: D12.2 L5.1 U4.21 | length 8.4
  Bottom Layer w0.254: L5.1@99.788,18.034 99.788,17.334 99.961,17.161 100.999,17.161 101.453,16.707 103.897,16.707 104.187,16.417 104.187,15.815 104.171,15.799 104.171,15.491 U4.21@104.164,15.484
  Bottom Layer w0.508: D12.2@98.552,18.88 98.598,18.834 98.988,18.834 99.042,18.78 99.742,18.78 99.788,18.734 L5.1@99.788,18.034
BUR: C30.1 R46.1 R47.1 U4.5 | length 5.7
  Bottom Layer w0.254: U4.5@106.314,12.834 107.284,12.834 107.433,12.685 107.433,12.514 107.95,11.996 108.908,11.996 108.908,11.882 108.982,11.808 108.982,11.252 109.058,11.176 109.172,11.176 109.248,11.1 109.664,11.1 109.728,11.036 R47.1@109.728,10.922 109.728,10.808 109.791,10.744 109.833,10.744 109.982,10.595 R46.1@109.982,10.068
CS: C31.2 R33.1 U4.9 | length 3.1
  Bottom Layer w0.254: U4.9@104.664,11.684 104.664,10.544 104.394,10.274 C31.2@104.394,10.16 104.394,10.046 104.457,9.982 104.572,9.982 104.994,9.56 R33.1@104.994,8.982
FB: C27.1 R40.1 R41.1 U4.6 | length 4.1
  Bottom Layer w0.254: U4.6@106.314,12.334 106.48,12.334 107.072,11.742 107.562,11.742 107.762,11.542 107.773,11.542 108.091,11.224 C27.1@108.091,11.11 R40.1@108.091,10.186 108.091,9.381 R41.1@108.042,9.332
FLT: C29.1 RT1.2 U4.1 | length 2.3
  Bottom Layer w0.254: U4.1@106.314,14.834 106.48,14.834 107.01,15.364 107.01,15.43 107.074,15.494 C29.1@107.188,15.494 107.251,15.557 107.505,15.557 107.632,15.684 107.823,15.684 107.95,15.811 RT1.2@107.95,16.002
GND: C1.2 C5.2 C6.2 C11.2 C12.2 C13.2 C14.2 C15.2 C16.2 C17.2 C20.2 C21.2 D3.4 D6.2 L1.13 NT1.2 R11.1 R12.1 R13.1 R14.1 R18.1 R21.1 R35.1 R36.1 T1.10 T1.11 TP2.1 TP3.2 TP7.1 U1.4 U2.3 U2.4 | length 206.4
  Top Layer w0.508: TP2.1@89.408,71.089 95.035,71.089 95.931,70.193 125.174,70.193 126.609,71.628 T1.10@127.114,71.628 ; T1.11@127.114,25.146 130.676,21.584 C21.2@130.676,19.358
  Top Layer w2.54: D3.4@36.068,8.209 37.846,6.431 C5.2@41.268,6.431 C6.2@41.268,26.497
  Signal Layer 1 w0.508: v1(38.354,45.547) 32.766,45.547 32.512,45.801 32.512,67.645 35.814,70.947 38.862,70.947 42.164,67.645 63.246,67.645 64.77,69.169 65.786,69.169 70.104,73.487 76.454,73.487 80.01,69.931 80.01,60.279 80.772,61.041 80.772,69.423 82.026,70.677 C11.2@82.296,70.677
  Bottom Layer w0.254: U2.4@88.884,47.527 U2.3@90.154,47.527 90.154,47.877 90.756,48.479 93.358,48.479 93.849,47.987 C20.2@93.964,47.987 ; NT1.2@107.95,20.828 108.176,21.054 v2(108.176,21.184)
  Bottom Layer w0.508: C15.2@76.454,62.273 76.579,62.398 79.452,62.398 79.944,61.906 U1.4@79.944,61.444 ; R18.1@79.794,57.485 C12.2@79.794,59.009 ; C12.2@80.01,59.225 80.01,61.378 U1.4@79.944,61.444 ; C13.2@83.749,61.444 U1.4@79.944,61.444
  Bottom Layer w1.016: v3(105.457,48.514) 105.506,48.563 105.506,49.362 105.548,49.404 C17.2@106.053,49.404
  Bottom Layer w2.54: v6(30.48,7.447) 31.242,8.209 D3.4@36.068,8.209 37.846,6.431 C5.2@41.268,6.431
  other v1: 32.004,28.783 34.036,28.783 34.29,48.341 35.306,48.341 36.322,48.341 37.338,48.341 38.354,48.341 34.29,49.357 35.306,49.357 36.322,49.357 37.338,49.357 38.354,49.357 82.296,55.961 82.296,56.977 83.058,56.977 74.676,60.533 80.518,62.393 30.48,72.719 78.74,73.233 30.48,73.914 78.232,73.995
  other v3: 70.701,6.749 92.694,38.664 92.752,40.235 92.83,41.795 92.889,43.366
  other v6: 94.636,29.806
  other v7: 89.519,47.527
GND_SEC: C21.1 C33.2 C34.2 C35.2 C36.2 C37.2 C38.2 C39.1 C40.2 C41.1 C42.2 C47.2 D16.2 Q9.3 R49.1 R50.1 R60.1 TP11.1 TP17.1 U6.2 U7.4 | length 0.9
  Bottom Layer w0.381: C41.1@146.436,11.668 v1(147.378,11.668)
  other v1: 154.653,2.456 152.298,16.025
  other v3: 172.782,63.5
HV: C1.1 C17.1 C18.1 D1.1 D2.1 R6.2 R19.2 R20.2 R24.2 T1.1 | length 149.2
  Signal Layer 1 w0.254: D2.1@36.83,61.803 41.021,65.994 63.93,65.994 65.454,67.518 66.47,67.518 68.289,69.337 73.033,69.337 76.327,66.042 76.327,54.818 v1(71.12,49.611)
  Signal Layer 2 w2.54: D2.1@36.83,61.803 45.974,61.803 72.39,35.387 72.39,35.306
  Bottom Layer w0.508: R6.2@69.416,49.611 v1(71.12,49.611)
  Bottom Layer w1.27: C18.1@100.345,72.011 100.345,71.989 100.076,71.721 R24.2@100.076,67.471 106.773,67.471 112.89,61.354 T1.1@112.89,57.277
  Bottom Layer w2.54: R20.2@69.85,21.881 69.621,26.878 D1.1@69.494,27.005 69.494,27.513 69.621,27.64 73.774,27.64 C1.1@74.328,28.194 R19.2@74.328,24.692
IC_GND: C26.2 C28.2 C29.2 C30.2 C31.1 C32.2 D15.2 NT1.1 NT2.1 Q4.2 Q7.2 R34.2 R39.1 R42.1 R43.1 R44.1 R45.2 R47.2 U3.2 U4.8 U4.17 U4.18 U4.25 U5.3 | length 38.9
  Top Layer w0.254: NT2.1@103.657,14.908 103.657,14.809 103.86,14.606 104.367,14.606 v4(104.414,14.559) ; v2(110.409,11.913) 127.733,11.913 129.802,9.843 U5.3@130.002,9.843
  Bottom Layer w0.254: Q4.2@91.795,14.021 92.52,14.021 93.347,13.194 94.315,13.194 95.243,14.123 v2(98.593,14.123) ; U4.8@105.164,11.684 105.164,10.957 105.41,10.711 C31.1@105.41,10.16 ; R39.1@107.95,19.142 NT1.1@107.95,20.32 ; v2(109.248,18.462) 109.248,18.503 109.503,18.758 109.503,18.917 109.96,19.374 Q7.2@111.953,19.374 ; Q7.2@111.953,19.313 111.953,18.055 112.597,17.411 113.005,17.411 U3.2@113.078,17.338 113.998,17.338 114.186,17.526 R34.2@114.3,17.526
  other v2: 106.368,8.608 105.41,10.67 100.156,11.413 109.387,14.894 107.188,16.51
  other v4: 104.414,12.609 103.439,13.584 104.414,13.584 105.389,13.584
IPC: R45.1 U4.4 | length 1.9
  Bottom Layer w0.254: U4.4@106.314,13.334 107.684,13.334 107.95,13.068 R45.1@107.95,12.954
NetC2_1: C2.1 L3.4 RV1.2 TP_N1.1 | length 35.8
  Top Layer w1.905: TP_N1.1@2.794,72.39 2.852,72.332 6.432,72.332 RV1.2@7.958,70.806 8.994,69.77 C2.1@13.74,69.77 14.087,69.423 19.204,69.423 20.32,68.307 20.32,52.752 L3.4@21.082,51.99
NetC2_2: C2.2 F1.2 L3.1 RV1.1 | length 23
  Top Layer w1.905: RV1.1@5.758,59.75 13.72,59.75 C2.2@13.74,59.77 13.74,52.348 L3.1@13.382,51.99 9.826,51.99 F1.2@7.366,49.53
NetC3_1: C3.1 L3.3 L4.4 | length 24
  Top Layer w1.905: L4.4@19.478,26.32 24.284,31.126 C3.1@24.284,36.83 21.082,40.032 L3.3@21.082,46.99
NetC3_2: C3.2 L3.2 L4.2 | length 22.3
  Top Layer w1.905: L4.2@9.478,26.32 9.478,30.475 11.784,32.781 C3.2@11.784,36.83 13.382,38.428 L3.2@13.382,46.99
NetC4_1: C4.1 D3.3 L4.7 | length 27
  Top Layer w1.905: C4.1@21.998,5.334 21.998,7.883 19.554,10.328 19.554,14.244 L4.7@19.478,14.32 35.011,14.32 36.042,13.289 D3.3@36.068,13.289
NetC4_2: C4.2 D3.2 L4.9 | length 37.3
  Top Layer w1.905: C4.2@9.498,5.334 9.498,14.3 L4.9@9.478,14.32 13.527,18.369 D3.2@36.068,18.369
NetC5_1: C5.1 D3.1 L2.1 | length 28.1
  Bottom Layer w2.54: D3.1@36.068,23.449 38.354,23.449 40.95,20.853 40.95,19.329 48.204,12.075 L2.1@50.292,12.075 50.624,12.075 C5.1@56.268,6.431
NetC6_1: C6.1 D1.2 L1.2 L2.2 | length 25.3
  Top Layer w2.54: L1.2@53.086,43.769 52.899,43.582 52.899,29.866 C6.1@56.268,26.497
  Bottom Layer w2.54: C6.1@56.268,26.497 62.23,26.497 62.357,26.624 D1.2@62.357,27.005
NetC7_2: C7.2 C8.1 C9.1 R5.1 R8.2 R10.1 | length 11.4
  Bottom Layer w0.508: R5.1@75.999,71.521 76.38,71.14 76.38,68.915 77.254,68.915 R8.2@77.47,69.131 C9.1@79.248,69.131 ; C7.2@76.38,65.867 76.38,68.587 ; R10.1@79.248,67.429 C9.1@79.248,69.131 ; C8.1@80.518,69.131 C9.1@79.248,69.131
NetC8_2: C8.2 C9.2 Q1.3 R4.1 R8.1 R11.2 R12.2 R13.2 R14.2 | length 98.6
  Bottom Layer w0.305: Q1.3@36.03,41.229 Q1.3@36.83,41.229
  Bottom Layer w0.508: R4.1@34.29,39.489 Q1.3@36.03,41.229 ; 38.354,43.589 38.354,44.531 38.1,44.785 33.528,44.785 32.512,45.801 32.512,67.645 35.814,70.947 38.862,70.947 42.164,67.645 63.246,67.645 64.77,69.169 65.786,69.169 70.104,73.487 76.454,73.487 77.978,71.963 77.978,70.731 ; R8.1@77.47,70.731 77.978,70.731 ; C8.2@80.518,70.731 C9.2@78.994,70.731 77.978,70.731
  Bottom Layer w1.27: R11.2@34.152,43.589 R12.2@36.946,43.589 38.354,43.589 R13.2@39.74,43.589 R14.2@42.534,43.589 ; Q1.3@36.83,41.229 R12.2@36.83,43.473
NetC10_1: C10.1 C12.1 U1.6 | length 3.7
  Bottom Layer w0.508: C10.1@76.746,59.009 C12.1@78.194,59.009 ; C12.1@78.044,59.159 U1.6@78.044,61.444
NetC10_2: C10.2 R18.2 | length 1.4
  Bottom Layer w0.508: C10.2@76.708,57.447 R18.2@78.156,57.447
NetC13_1: C13.1 R17.1 U1.3 | length 6.1
  Bottom Layer w0.508: U1.3@79.944,64.194 83.241,64.194 C13.1@83.82,64.773 84.328,65.281 84.328,65.867 R17.1@84.836,66.375
NetC14_1: C14.1 R10.2 U1.2 | length 5
  Bottom Layer w0.508: R10.2@78.994,65.575 U1.2@78.994,64.194 78.994,63.581 79.464,63.111 C14.1@81.788,63.111
NetC15_1: C15.1 R16.1 R21.2 U1.1 | length 6.8
  Top Layer w0.508: R16.1@77.978,61.079 R21.2@77.978,62.349 ; R21.2@77.978,62.781 v1(77.978,65.359)
  Bottom Layer w0.508: C15.1@76.454,63.873 77.723,63.873 U1.1@78.044,64.194 78.044,65.293 v1(77.978,65.359)
NetC18_2: C18.2 Q5.2 R24.1 | length 15
  Bottom Layer w1.27: R24.1@100.076,64.771 100.23,64.771 100.315,64.686 100.315,60.929 ; 100.33,60.914 100.315,60.929 ; C18.2@100.345,62.011 100.329,61.995 100.329,60.943 100.315,60.929
  Bottom Layer w1.524: Q5.2@100.33,53.594 100.315,53.609 99.389,53.609 97.879,55.119 97.879,58.463 100.33,60.914
NetC19_1: C19.1 D8.1 U2.5 | length 4.9
  Bottom Layer w0.508: D8.1@86.868,53.494 D8.1@87.193,53.494 ; D8.1@87.559,53.86 D8.1@87.193,53.494 ; C19.1@89.092,54.795 C19.1@89.105,54.795 89.105,53.728 88.892,53.515 88.892,52.935 U2.5@88.884,52.927 88.884,53.265 88.655,53.494 D8.1@87.193,53.494
NetC20_1: C20.1 D10.3 U2.1 | length 3.8
  Bottom Layer w0.254: D10.3@92.434,45.239 92.434,46.837 92.694,47.097 U2.1@92.694,47.257 ; U2.1@92.694,47.527 U2.1@92.694,47.257 ; C20.1@93.964,46.971 93.278,46.971 93.129,47.12 92.83,47.12 U2.1@92.694,47.257
NetC24_1: C24.1 C25.1 D12.1 Q3.2 R25.2 TP4.1 U4.19
NetC39_2: C39.2 R48.2 | length 2
  Bottom Layer w0.635: R48.2@171.323,51.054 C39.2@173.355,51.054
NetC40_1: C40.1 U6.3 | length 1.8
  Bottom Layer w0.254: U6.3@170.329,58.862 170.329,59.436 170.773,59.88 170.964,59.88 171.091,60.008 C40.1@171.091,60.198
NetC43_1: C43.1 C44.2 C46.1 R55.1 R60.2 U7.2 | length 6.6
  Bottom Layer w0.254: U7.2@148.99,15.933 148.983,15.94 148.983,17.249 C43.1@148.976,17.256 148.976,18.234 C46.1@149.23,18.488 150.323,18.488 150.5,18.666 R60.2@150.5,18.78 R55.1@150.5,19.923 150.581,20.004 150.581,21.147 C44.2@150.662,21.228
NetC43_2: C43.2 D17.1 R57.1 TP15.1 U7.1 | length 13.9
  Bottom Layer w0.635: D17.1@141.478,12.813 TP15.1@141.478,15.743 144.9,19.165 146.116,19.165 146.611,18.67 147.676,18.67 147.833,18.513 R57.1@147.833,18.488 147.96,18.361 C43.2@147.96,17.256 147.738,17.033 147.738,15.951 U7.1@147.72,15.933 147.72,15.761 U7.1@147.703,15.743
NetC44_1: C44.1 R53.1 | length 1.2
  Bottom Layer w0.254: C44.1@150.662,22.428 R53.1@151.862,22.428
NetC45_2: C45.2 R59.2 | length 0.5
  Bottom Layer w0.635: R59.2@142.118,4.21 C45.2@142.626,4.21
NetC46_2: C46.2 R57.2 | length 1.4
  Bottom Layer w0.635: R57.2@147.833,20.088 C46.2@149.23,20.088
NetC47_1: C47.1 R56.1 R61.2 R62.2 TP16.1 U7.3 | length 14.3
  Bottom Layer w0.254: C47.1@150.246,17.51 150.253,17.503 150.253,15.94 U7.3@150.26,15.933 150.26,15.508 151.378,14.391 R62.2@152.803,14.391 R61.2@154.145,14.391
  Bottom Layer w0.762: TP16.1@145.42,17.51 145.42,15.221 146.182,14.459 R56.1@146.182,14.434 149.162,14.434 150.179,15.451 U7.3@150.179,15.589
NetC48_1: C48.1 C49.2 D18.1 TP18.1 U7.7 | length 11.5
  Bottom Layer w0.254: TP18.1@146.53,4.21 144.594,6.145 144.594,6.927 D18.1@144.264,7.258 145.149,7.258 146.092,8.201 C48.1@146.283,8.201 146.473,8.201 146.819,8.547 146.819,8.634 147.011,8.825 148.171,8.825 148.338,8.658 C49.2@149.103,8.658 148.99,8.771 U7.7@148.99,10.483
NetC48_2: C48.2 R67.2 | length 1.3
  Bottom Layer w0.254: C48.2@146.283,6.677 146.304,6.699 147.569,6.699 R67.2@147.591,6.72
NetC49_1: C49.1 R62.1 R64.1 R66.2 R67.1 TP19.1 U7.6 | length 19
  Bottom Layer w0.254: R67.1@147.591,8.244 147.718,8.117 148.069,8.117 C49.1@149.103,7.083 ; C49.1@149.103,7.058 C49.1@149.103,7.083 ; TP19.1@150.825,4.381 150.825,7.949 R64.1@150.662,8.112 ; R62.1@152.803,12.891 152.68,12.768 152.12,12.768 150.26,10.908 U7.6@150.26,10.483 150.26,9.964 150.662,9.562 150.662,8.981 ; R66.2@155.401,9.364 151.046,9.364 150.662,8.981 ; C49.1@149.103,7.083 149.959,7.939 150.489,7.939 R64.1@150.662,8.112 ; R64.1@150.662,8.112 150.662,8.981
NetD4_1: D4.1 R7.2 | length 2.5
  Bottom Layer w0.508: R7.2@31.242,37.889 31.242,36.657 32.004,35.895 D4.1@32.174,35.895
NetD4_2: D4.2 Q1.1 R3.2 R4.2 | length 5.6
  Bottom Layer w0.508: R3.2@32.766,37.889 R4.2@34.29,37.889 D4.2@34.29,35.979 ; D4.2@34.374,35.895 Q1.1@36.576,35.895
NetD6_1: D6.1 Q2.1 R23.1 | length 4.9
  Bottom Layer w1.27: Q2.1@72.15,9.8 72.15,9.37 72.285,9.235 72.715,9.235 73.118,8.832 D6.1@73.965,8.832 74.328,9.195 R23.1@74.328,11.121
NetD7_2: D7.2 Q3.3 | length 1.5
  Bottom Layer w0.508: D7.2@93.075,18.606 Q3.3@94.541,18.606
NetD8_2: D8.2 R27.2 | length 1.6
  Bottom Layer w0.381: R27.2@86.868,47.833 D8.2@86.868,49.414
NetD11_1: D11.1 Q7.3 | length 1.9
  Bottom Layer w0.762: D11.1@111.365,22.352 111.365,22.199 111.442,22.123 112.592,22.123 112.903,21.812 Q7.3@112.903,21.774
NetD14_2: D14.2 Q8.2 R37.2 | length 29.6
  Signal Layer 2 w0.254: v2(94.205,36.839) 96.991,36.839 97.19,36.64 97.19,14.662 v2(98.813,13.039)
  Bottom Layer w0.254: D14.2@93.345,36.914 93.42,36.839 v2(94.205,36.839) 94.991,36.839 Q8.2@95.066,36.764 ; v2(98.813,13.039) 98.842,13.068 99.208,13.068 R37.2@99.27,13.13
NetD16_1: D16.1 Q10.1 R54.1 | length 4.6
  Bottom Layer w0.635: D16.1@155.326,4.656 155.538,4.867 157.471,4.867 Q10.1@157.554,4.95 ; R54.1@157.554,2.794 Q10.1@157.554,4.95 ; Q10.1@157.654,5.05 Q10.1@157.554,4.95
